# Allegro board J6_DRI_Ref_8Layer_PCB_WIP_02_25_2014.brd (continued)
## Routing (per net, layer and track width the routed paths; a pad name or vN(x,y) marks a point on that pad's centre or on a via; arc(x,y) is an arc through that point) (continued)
VEVM_5V0: length 5.2
  TOP w0.203: U45.A6 v1(128.31,71.88) ; U45.A9 125.98,71.83
  TOP w0.254: v1(124.78,72.22) U45.A10
  TOP w0.381: C99.2 v2(125.55,69.8) 125.55,70.94 125.98,71.38 125.98,71.83
VIO_PMIC: length 2.4
  TOP w0.254: U45.D9 v1(125.58,74.62)
  TOP w0.381: R192.2 v2(123.14,69.8)
  BOTTOM w0.203: v1(125.58,81.82) 125.46,81.7 R533.1
VOUT1_INTB: length 18
  TOP w0.102: 79.2,62.05 77.55,62.05 77.15,61.66 U52.B11
  TOP w0.127: 79.2,62.05 79.32,61.93 82.31,61.93 82.7,62.31 84.37,62.31 85.19,61.48 86.14,61.48 87.28,62.63 93.96,62.63
VPP: length 0.5
  TOP w0.102: U52.K14 v1(71.11,59.65)
VRTC_OUT: length 0.9
  BOTTOM w0.254: v2(126.7,85.8) 126.82,85.68 R514.1
VTT_DDR: length 0.6
  TOP w0.305: C165.1 65.86,30.56
  vias: v2(63.02,17.48) v2(64.8,17.99) v2(65.56,29.03) v2(66.09,18.27) v2(66.95,29.03) v2(106.58,28.53) v2(107.34,29.29)
VUSB_3V3: length 5.9
  TOP w0.127: U52.AA12 U52.Y12
  TOP w0.178: U52.Y12 v1(63.14,61.27)
  TOP w0.203: 125.23,71.77 125.59,72.13 125.59,73.03 U45.B9
  TOP w0.381: 125.23,71.77 124.79,71.33 v1(124.41,71.33) ; v2(124.41,69.8) C433.1
  BOTTOM w0.203: v1(63.14,61.27) 63.8,61.27 C489.1
XTAL1: length 18.9
  TOP w0.127: Y4.3 132.54,64.37 132.54,62.44 132.09,61.99 Y4.1 ; U45.A3 131.06,72.34 131.06,71.99 134.06,68.99 134.06,62.44 133.17,61.55 Y4.1 ; Y4.1 C115.1
XTAL2: length 19
  TOP w0.127: Y4.2 136.29,61.11 135.84,60.66 135.84,58.73 135.46,58.35 ; Y4.2 135.2,61.55 134.32,62.44 134.32,69.12 131.32,72.11 131.32,72.36 U45.A2 ; Y4.2 C116.1
ZQ_DBYTE1: length 4.2
  BOTTOM w0.127: U115.H8 92.99,24.67 89.97,24.67 R694.1
ZQ_DBYTE2: length 4.1
  TOP w0.127: U69.H8 98.58,24.66 99.34,24.66 100.16,25.48 R289.1
ZQ_DBYTE3: length 4.2
  BOTTOM w0.127: R695.1 75.62,24.67 78.64,24.67 U116.H8
ZQ_DBYTE4: length 4.4
  TOP w0.127: R288.1 85.81,25.48 84.99,24.66 84.23,24.66 U68.H8
ZQ_DBYTE4_1: length 1.3
  TOP w0.127: v1(59.05,24.65) U67.H8
  BOTTOM w0.127: R693.1 v1(59.05,24.65)
N35610: length 1.3
  TOP w0.127: U65.L8 v1(35.08,24.89)
  BOTTOM w0.127: R692.1 v1(35.08,24.89)
N35614: length 1.3
  TOP w0.127: U66.L8 v1(47.78,24.89)
  BOTTOM w0.127: R691.1 v1(47.78,24.89)
N17551426: length 0.6
  TOP w0.102: U45.D8 126.78,75.02 v1(126.38,75.42)
N17551447: length 0.6
  TOP w0.254: v1(128.78,77.02) 128.38,77.42 U45.G6
N17551455: length 1.6
  TOP w0.254: U45.C1 132.38,74.22 v1(132.78,73.82)
  BOTTOM w0.305: C403.2 v1(132.78,73.82)
N17551519: length 8.2
  TOP w0.127: U45.A11 124.03,72.27 124.03,71.58 123.52,71.07 123.52,70.31 123.77,70.06 123.77,65.57 R207.2
N17551551: length 0.6
  TOP w0.102: v1(128.78,79.42) 129.18,79.02 U45.J5
N17551822: length 0.6
  TOP w0.102: U45.E6 128.38,75.82 v1(128.78,75.42)
N17551928: length 1.5
  TOP w0.254: v1(127.98,73.82) U45.B7
  BOTTOM w0.305: C100.2 v1(127.98,73.82)
N18507369: length 4.8
  TOP w0.254: v1(127.18,73.82) 127.58,74.22 U45.C7
  TOP w0.381: R193.2 v2(126.7,69.8)
  BOTTOM w0.254: C432.2 127.18,71.17 127.74,71.73 127.74,72.57 127.18,73.12 v1(127.18,73.82)
N19066656: length 8.2
  TOP w0.127: TP42.1 126.11,66.42 126.11,70.23 126.57,70.69 126.57,71.71 126.39,71.88 126.39,73.03 U45.B8
N20019184: length 2.3
  BOTTOM w0.127: C601.1 R685.2 R688.2
N20082076: length 6.2
  TOP w0.127: TP30.1 134.95,83.97 133.43,82.45 133.43,80.86 U45.K1
N20307647: length 0.6
  TOP w0.102: U45.J7 127.58,79.02 v1(127.18,79.42)
N24036072: length 2.3
  BOTTOM w0.127: R687.2 R684.2 C599.1
N27151094: length 0.7
  TOP w0.102: v1(57.61,59.84) U52.AF14
N35662197: length 0.6
  TOP w0.102: v1(123.18,82.62) U45.N12
N42624965: length 0.6
  TOP w0.102: v1(129.59,75.42) U45.E5
N47347830: length 3.2
  TOP w0.102: v1(127.18,78.62) U45.H8
  BOTTOM w0.102: 127.58,79.02 129.15,79.02
  BOTTOM w0.127: v1(127.18,78.62) 127.58,79.02 ; 129.15,79.02 R709.2
N47347885: length 2.7
  TOP w0.102: v1(131.18,81.82) U45.M3
  BOTTOM w0.127: R708.2 132.56,81.85 132.56,81.54 132.38,81.36 131.65,81.36 v1(131.18,81.82)

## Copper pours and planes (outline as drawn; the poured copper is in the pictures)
GND on BOTTOM (solid shape): 33.79,18.48 34.08,18.2 34.48,18.2 34.48,17.95 33.23,17.95 33.23,17.99 33.2,18.07 33.15,18.13 33.03,18.25 32.98,18.29 32.92,18.32 32.89,18.33 32.89,18.42 33.36,18.42 33.68,18.73 33.79,18.73
GND on BOTTOM (solid shape): 40.21,39.69 40.3,39.63 40.28,39.52 38.83,38.06 37.05,38.06 37.05,39.56 37,39.6 36.99,39.66 37.04,39.69
GND on BOTTOM (solid shape): 48.74,48.83 48.8,48.84 48.83,48.79 48.83,48.7 40.35,40.22 34.11,40.22 34.02,40.29 34.04,40.4 34.32,40.68 40.6,40.68
GND on BOTTOM (solid shape): 63.9,46.43 64.01,46.45 64.07,46.36 64.07,46.23 62.74,44.9 61.71,44.9 60.83,44.02 60.78,44 60.74,44.05 60.74,44.16 61.99,45.4 62.87,45.4
GND on BOTTOM (solid shape): 70.4,45.37 70.46,45.46 70.57,45.44 70.6,45.4 72.97,45.4 73.06,45.31 73.07,45.26 73.02,45.23 71.3,45.23 71.05,44.98 70.67,44.98 70.4,45.25
GND on BOTTOM (solid shape): 59.4,19.8 59.47,19.89 59.58,19.86 60.42,19.01 62.68,19.01 62.7,18.95 62.69,18.86 62.61,18.81 60.36,18.81 59.4,19.77
GND on BOTTOM (solid shape): 87.72,34.7 87.78,34.79 87.89,34.77 87.9,34.76 88.56,34.76 88.84,34.48 89.09,34.48 89.09,34 89.17,33.92 89.2,33.81 89.1,33.75 88.66,33.75 88.08,34.33 87.72,34.33
GND on BOTTOM (solid shape): 40.85,25.78 40.97,25.8 41.03,25.7 41.03,25.62 40.76,25.34 39.95,25.34 39.21,24.6 37.36,24.6 37.26,24.67 37.29,24.78 37.8,25.29 39.58,25.29 39.88,25.59 40.67,25.59
GND on BOTTOM (solid shape): 60.86,22.16 60.9,22.13 60.9,22.08 60.87,22.05 60.85,22.01 60.63,21.8 60.62,21.79 60.36,21.63 60.33,21.32 60.34,21.31 60.34,21.25 60.2,21.25 59.37,22.09 59.4,22.16
GND on BOTTOM (solid shape): 43.33,24.83 43.4,24.91 43.51,24.88 43.84,24.55 45.26,24.55 45.52,24.29 45.52,24.26 45.52,24.15 45.56,24.04 45.56,23.94 45.47,23.89 44.25,23.89 43.45,24.69 43.43,24.69 43.35,24.73 43.33,24.82
GND on BOTTOM (solid shape): 62.68,23.51 62.7,23.46 62.72,23.41 62.71,23.31 62.63,23.26 61.57,23.26 61.13,22.82 61.08,22.82 61,22.87 60.98,22.96 60.99,23.04 60.98,23.13 61,23.22 61.08,23.26 61.14,23.26 61.44,23.55 62.68,23.55
GND on BOTTOM (solid shape): 55.38,19.11 55.49,19.13 55.55,19.03 55.55,18.98 55.56,18.92 55.54,18.84 55.46,18.8 51.41,18.8 51.39,18.82 51.38,18.88 51.43,18.91 51.82,18.91 52,19.09 52.25,19.09 52.43,18.91 53,18.91 53.18,19.09 53.43,19.09 53.61,18.91 54.18,18.91 54.36,19.09 54.51,19.09 54.69,18.91 55.17,18.91
GND on BOTTOM (solid shape): 89.11,35.13 89.55,35.13 89.65,35.15 89.74,35.21 89.85,35.33 89.9,35.27 90.02,35.16 89.83,34.96 89.83,34.62 89.85,34.52 89.9,34.43 89.97,34.37 89.93,34.33 89.86,34.29 89.81,34.25 89.62,34.25 89.62,34.73 89.34,35.02 89.06,35.02 88.78,35.3 88.37,35.3 88.27,35.36 88.3,35.47 88.53,35.71
GND on BOTTOM (solid shape): 51.35,25.58 51.37,25.52 51.4,25.47 51.56,25.31 51.64,25.31 51.73,25.27 51.74,25.17 51.7,25 51.74,24.82 51.73,24.72 51.64,24.68 51.08,24.68 50.92,24.53 50.29,24.53 50.14,24.68 50.11,24.68 50.07,24.71 50.08,24.77 50.93,25.62 51.34,25.62
GND on BOTTOM (solid shape): 34.78,19.9 34.83,19.84 34.89,19.79 34.89,19.55 35.2,19.24 37.19,19.24 37.57,19.62 38.2,19.62 38.53,19.29 39.12,19.29 39.4,19.57 39.6,19.57 39.83,19.34 39.85,19.23 39.76,19.17 38.99,19.17 38.63,18.81 37.67,18.81 37.42,19.07 36.5,19.07 36.32,18.89 36.1,18.89 35.92,19.07 34.98,19.07 34.91,19.13 34.91,19.37 34.55,19.73 34.53,19.84 34.62,19.9
GND on BOTTOM (solid shape): 26.31,28.42 26.42,28.44 26.48,28.35 26.48,27.32 26.79,27.01 27.7,27.01 28.51,27.83 28.84,27.83 28.93,27.77 28.91,27.65 28.82,27.57 28.82,26.99 28.59,26.76 26.69,26.76 26.47,26.92 26.2,26.94 26.11,26.96 26.07,27.04 26.07,28.19
GND on BOTTOM (solid shape): 38.8,47.47 38.8,47.3 38.82,47.2 38.88,47.11 39,46.98 39.09,46.92 39.19,46.9 39.4,46.9 39.49,46.92 39.58,46.97 39.59,46.99 39.66,46.99 39.66,46.92 39.68,46.81 39.74,46.73 39.76,46.71 39.77,46.65 39.73,46.62 39,46.62 38.43,47.19 36.76,47.19 36.53,46.95 35.75,46.95 35.75,47.24 35.82,47.31 36.25,47.31 36.51,47.56 38.7,47.56
GND on BOTTOM (solid shape): 46.42,38.58 46.7,38.29 47.26,38.29 47.3,38.2 47.3,38.15 47.26,38.13 46,38.13 45.91,38.03 45.82,38 45.75,38.05 45.36,38.26 44.97,38.03 44.9,37.98 44.81,38.01 44.77,38.05 45.53,38.8 46.42,38.8
GND on BOTTOM (solid shape): 51.44,40.71 51.53,40.74 51.6,40.69 51.65,40.63 51.69,40.57 51.87,40.39 51.98,40.31 52.11,40.24 52.17,40.17 52.14,40.08 51.4,39.34 50.68,39.34 49.94,38.6 48.28,38.6 48.19,38.57 48.12,38.63 48.1,38.65 48.11,38.75 48.19,38.8 48.29,38.8 48.58,39.08 48.58,39.28 50.02,39.28
GND on BOTTOM (solid shape): 30.12,36.7 30.23,36.72 30.29,36.63 30.29,33.75 29.18,33.75 28.81,33.38 28.78,33.34 28.75,33.29 28.7,33.24 28.63,33.23 28.47,33.23 28.33,33.16 28.32,33.15 28.25,33.15 28.02,33.38 27.7,33.4 27.61,33.41 27.57,33.49 27.57,34.16
GND on BOTTOM (solid shape): 22.98,28.89 23.07,28.89 23.12,28.84 23.14,28.77 23.11,28.7 22.54,28.13 22.54,27.4 22.73,27.21 22.75,27.1 22.66,27.04 22.56,27.04 22.45,27.02 22.37,26.96 22.16,26.76 22.16,26.5 22.1,26.4 21.99,26.42 21.85,26.56 21.98,26.69 22.04,26.77 22.06,26.88 22.06,28.87 22.55,28.87 22.78,29.1
GND on BOTTOM (solid shape): 70.12,44.53 70.18,44.62 70.29,44.6 70.44,44.45 71.11,44.45 71.19,44.41 71.21,44.32 71.22,43.93 71.45,43.62 71.45,43.15 71.19,42.71 71.33,42.21 71.34,42.2 71.34,42.13 71.18,42.13 70.12,43.19
GND on BOTTOM (solid shape): 39.98,22.5 39.96,22.48 39.84,22.13 40.03,21.81 40.03,21.53 39.85,21.25 39.91,20.92 39.91,20.82 39.82,20.77 39.47,20.77 39.25,20.99 36.62,20.99 36.55,21.05 36.53,21.16 36.63,21.22 38.51,21.22 39.86,22.57 39.98,22.57
GND on BOTTOM (solid shape): 43.41,20.21 43.5,20.15 43.49,20.05 43.46,20 43.44,19.94 43.38,19.88 43.3,19.88 42.9,19.84 42.79,19.45 42.78,19.36 42.7,19.32 42.31,19.32 41.98,18.99 40.08,18.99 39.99,19.08 39.98,19.13 40.03,19.17 42.01,19.17 43.06,20.21
GND on BOTTOM (solid shape): 34.53,19.21 34.53,18.97 34.6,18.91 34.62,18.8 34.52,18.74 34.49,18.74 34.4,18.78 34.39,18.87 34.26,19.29 33.83,19.27 33.46,19.27 33.14,18.95 32.56,18.95 32.48,19.03 32.47,19.08 32.52,19.12 33.16,19.12 33.45,19.41 33.47,19.41 33.62,19.46 33.73,19.57 34.17,19.57
GND on BOTTOM (solid shape): 33.73,25.91 33.84,25.91 33.92,25.87 33.94,25.78 33.94,25.6 34.03,25.45 34.05,25.37 34.02,25.3 33.95,25.22 33.9,25.13 33.89,25.1 33.73,25.1 33.71,25.13 33.47,25.38 33.12,25.38 33.03,25.39 32.98,25.46 32.7,25.75 32.36,25.75 32.27,25.81 32.29,25.92 32.34,25.97 33.66,25.97
GND on BOTTOM (solid shape): 79.45,21.27 79.53,21.23 79.55,21.14 79.55,20.97 79.64,20.83 79.64,20.65 80.97,19.32 81.64,19.32 81.67,19.27 81.72,19.23 81.75,19.12 81.65,19.05 80.74,19.05 80.66,19.09 80.64,19.18 80.55,19.5 80.24,19.61 80.21,19.6 79.22,20.59 79.22,20.83 79.32,20.97 79.32,21.14 79.33,21.23 79.42,21.27
GND on BOTTOM (solid shape): 93.8,21.27 93.88,21.23 93.9,21.14 93.9,20.97 93.99,20.83 93.99,20.65 95.32,19.32 95.99,19.32 96.03,19.27 96.07,19.23 96.1,19.12 96,19.05 95.09,19.05 95.01,19.09 94.99,19.18 94.9,19.5 94.59,19.61 94.56,19.6 93.57,20.59 93.57,20.83 93.67,20.97 93.67,21.14 93.69,21.23 93.77,21.27
GND on BOTTOM (solid shape): 24.72,22.31 24.79,22.28 25.5,21.58 27.18,21.58 27.26,21.53 27.27,21.44 27.31,21.09 27.63,20.95 27.65,20.96 28.12,20.49 28.85,20.49 29.05,20.28 29.09,20.28 29.11,20.22 28.85,19.95 28.58,19.95 28.41,20.13 27.88,20.13 27.7,19.95 25.79,19.95 25.62,20.13 25.62,20.59 25.32,20.88 24.86,20.88 24.51,21.24 24.51,21.29 24.67,21.45 24.73,21.53 24.75,21.63 24.75,21.8 24.73,21.9 24.67,21.99 24.59,22.07 24.56,22.15 24.59,22.22 24.62,22.25 24.64,22.27
GND on BOTTOM (solid shape): 30.14,32.59 30.38,32.42 30.68,32.43 30.69,32.44 30.75,32.44 30.75,32.32 29.91,31.49 29.83,31.46 29.76,31.5 29.46,31.64 29.18,31.46 29.17,31.44 29.09,31.44 29.04,31.47 29.05,31.52 29.19,31.66 29.22,31.69 29.24,31.72 29.29,31.77 29.36,31.77 29.77,31.9 29.74,32.32 29.74,32.48 29.8,32.53 29.85,32.59
GND on BOTTOM (solid shape): 77.16,35.98 77.19,35.88 77.13,35.81 76.84,35.44 77.03,35.01 77.03,34.78 76.65,34.41 76.06,34.41 76,34.46 75.98,34.57 76.07,34.63 76.47,34.63 76.67,34.83 76.73,34.92 76.75,35.02 76.75,35.19 76.73,35.29 76.67,35.38 76.53,35.51 76.67,35.65 76.73,35.73 76.75,35.83 76.75,36 76.73,36.1 76.67,36.19 76.64,36.21 76.62,36.33 76.72,36.39 76.75,36.39
GND on BOTTOM (solid shape): 53.94,47.51 54.02,47.48 54.04,47.39 54.07,47.17 54.22,47.01 54.22,47 54.38,46.85 54.37,46.82 54.36,46.73 54.36,46.63 54.37,46.61 54.03,46.27 54.01,46.27 53.35,45.91 53.47,45.17 53.52,45.12 53.53,45.07 53.48,45.04 52.66,45.04 52.47,44.85 52.32,44.99 52.34,45.03 52.39,45.48 52.02,45.75 51.93,45.81 51.96,45.92 52.97,46.93 53.17,46.93 53.76,47.51
GND on BOTTOM (solid shape): 82.26,20.92 82.37,20.94 82.44,20.84 82.44,20.67 82.28,20.29 82.59,20.02 82.6,20.02 82.65,19.98 82.58,19.87 82.55,19.87 82.43,19.84 82.33,19.77 82.26,19.74 82.19,19.77 81.9,19.86 81.64,19.7 81.13,19.7 80.76,20.07 80.75,20.13 80.8,20.16 80.85,20.16 81.2,20 81.49,20.25 81.55,20.31 81.62,20.31 81.98,20.4 82.08,20.75 82.1,20.84 82.18,20.88 82.23,20.88
GND on BOTTOM (solid shape): 96.61,20.92 96.72,20.94 96.79,20.84 96.79,20.67 96.63,20.29 96.94,20.02 96.95,20.02 97,19.98 96.93,19.87 96.9,19.87 96.78,19.84 96.68,19.77 96.61,19.74 96.54,19.77 96.25,19.86 95.99,19.7 95.48,19.7 95.11,20.07 95.1,20.13 95.15,20.16 95.2,20.16 95.55,20 95.85,20.25 95.9,20.31 95.98,20.31 96.33,20.4 96.43,20.75 96.45,20.84 96.53,20.88 96.58,20.88
GND on BOTTOM (solid shape): 34.35,42.1 34.63,42.1 34.73,42.12 34.82,42.18 34.95,42.31 35.08,42.18 35.17,42.12 35.27,42.1 35.44,42.1 35.54,42.12 35.63,42.18 35.76,42.31 35.9,42.18 35.98,42.12 36.09,42.1 36.25,42.1 36.36,42.12 36.44,42.18 36.58,42.31 36.71,42.18 36.8,42.12 36.9,42.1 37.07,42.1 37.17,42.12 37.26,42.18 37.39,42.31 37.52,42.18 37.61,42.12 37.71,42.1 37.88,42.1 37.98,42.12 38.07,42.18 38.2,42.31 38.34,42.18 38.42,42.12 38.52,42.1 38.69,42.1 38.79,42.12 38.88,42.18 39.02,42.32 39.16,42.18 39.24,42.12 39.34,42.1 40.07,42.1 40.07,41.75 40.35,41.47 40.39,41.47 40.48,41.4 40.46,41.29 40.38,41.21 34.1,41.21 33.92,41.03 33.81,41.01 33.74,41.1 33.74,42.36 34.1,42.36
GND on BOTTOM (solid shape): 31.69,18.14 31.74,18.06 31.74,17.7 32.02,17.41 32.57,17.41 32.76,17.61 32.88,17.49 32.96,17.43 33.07,17.41 33.43,17.41 33.52,17.36 33.5,17.25 33.72,16.52 34.31,17 34.37,17.1 34.49,17.08 34.51,17.06 35.52,17.06 35.58,17.12 35.62,17.07 35.63,17.06 36.18,16.73 36.51,17.29 36.53,17.37 36.61,17.41 39.19,17.41 39.32,17.54 39.59,17.54 39.72,17.41 42.03,17.41 42.11,17.37 42.13,17.29 42.13,17.06 42.23,16.87 42.25,16.77 42.18,16.7 41.99,16.61 41.84,16.46 41.37,16.46 40.64,16.7 40.2,16.08 40.2,15.83 40.22,15.64 40.3,15.48 40.3,15.37 40.21,15.32 30.12,15.32 30.02,15.38 30.05,15.49 30.19,15.7 30.24,15.95 30.24,16.21 30.18,16.48 30.01,16.7 29.98,16.8 30.04,16.87 30.28,17.1 30.31,17.43 30.32,17.52 30.4,17.57 30.93,17.57 31.51,18.14 31.56,18.15 31.6,18.16
GND on BOTTOM (solid shape): 63.75,45.15 63.86,45.17 63.92,45.08 63.92,39.87 63.88,39.8 63.8,39.77 63.63,39.77 63.47,39.7 63.39,39.68 63.33,39.72 63.1,39.9 62.81,39.97 62.56,39.97 62.27,39.9 62.05,39.72 61.98,39.68 61.91,39.7 61.65,39.78 61.39,39.7 61.28,39.69 61.23,39.78 61.23,40.32 61,40.55 61,42.06 61.04,42.14 61.13,42.16 61.32,42.15 61.5,42.22 61.58,42.24 61.64,42.2 61.7,42.13 61.77,42.07 61.77,41.6 61.54,40.87 62.15,40.43 62.41,40.43 63.02,40.87 62.79,41.6 62.79,42.07 63.02,42.8 62.41,43.25 62.15,43.25 61.87,43.18 61.64,42.99 61.58,42.96 61.5,42.97 61.32,43.05 61.13,43.04 61.04,43.06 61,43.14 61,43.43 61.64,44.07 61.74,44.1 61.81,44.03 62.36,43.7 62.7,44.24 62.72,44.33 62.8,44.36 62.96,44.36
GND on BOTTOM (solid shape): 99.49,31.75 99.58,31.74 99.63,31.66 99.63,29.89 99.59,29.8 99.5,29.79 99.44,29.81 99.38,29.81 99.31,29.83 99.28,29.9 98.76,30.05 98.99,29.56 99.03,29.54 99.04,29.5 99.04,29.44 98.96,29.36 98.94,29.36 98.77,28.85 99.28,29.02 99.28,29.04 99.37,29.12 99.44,29.13 99.5,29.14 99.59,29.13 99.63,29.05 99.63,28.61 99.4,28.39 99.32,28.36 99.24,28.41 98.95,28.56 98.7,28.34 98.62,28.27 98.53,28.3 98.47,28.35 98.46,28.36 98.15,28.56 97.89,28.3 97.85,28.23 97.79,28.21 97.78,28.21 97.71,28.23 97.68,28.3 97.64,28.41 97.56,28.5 97.52,28.57 97.55,28.65 97.63,28.73 97.63,28.89 97.66,28.94 97.67,28.98 97.74,29.05 97.84,29.02 97.9,28.97 97.9,28.96 98.4,28.85 98.29,29.34 98.28,29.34 98.22,29.4 98.19,29.5 98.26,29.57 98.48,29.91 98.16,30.16 98.09,30.19 98.06,30.26 98.09,30.33 98.16,30.36 98.37,30.43 98.48,30.62 98.48,30.64 98.57,30.72 98.63,30.73 98.67,30.71 98.69,30.67 99.14,30.4 99.11,30.93 99.05,31.01 99.08,31.1 99.42,31.43 99.42,31.72
GND on BOTTOM (solid shape): outline of 483 points within 42.72,15.32 63.52,19.5
GND on BOTTOM (solid shape): outline of 1981 points within 82.98,18.37 97.86,36.87
GND on BOTTOM (solid shape): outline of 3469 points within 55.35,15.32 85.24,41
GND on L2-GND1, L7-GND2: 169.24,181.94 169.24,13.46 0.76,13.46 0.76,181.94
VDD_CORE on TOP, BOTTOM: 129.62,89.74 133.81,89.74 134.32,90.25 134.32,95.33 133.93,95.71 129.49,95.71 129.11,95.33 129.11,90.25
VDD_CORE on L4-PWR1: 69.04,61.04 80.34,72.34 99.26,72.34 111.71,84.79 133.81,84.79 134.32,85.3 134.32,95.71 133.81,96.22 129.24,96.22 128.73,95.71 128.73,92.28 107.77,92.28 95.58,80.09 67.64,80.09 60.78,73.23 60.78,64.09 63.7,61.17 63.7,58.24 63.96,57.99 64.34,57.99 64.59,57.74 64.59,55.58 64.85,55.32 65.74,55.32 65.99,55.58 65.99,57.23 66.37,57.61 66.88,57.61 69.04,59.77
VDD_CORE on L5-PWR2: 68.66,60.02 65.61,60.02 65.35,59.77 65.35,58.24 65.99,57.61 65.99,56.09 66.12,55.96 71.32,55.96 71.45,56.09 71.45,57.61 71.58,57.74 72.34,57.74 72.34,60.53 72.09,60.78 71.32,60.78 71.07,60.53 71.07,59.77 70.82,59.51 69.16,59.51
VDD_DDR on TOP: 116.03,79.45 116.03,83.9 115.77,84.15 112.22,84.15 111.71,83.64 111.71,79.83 112.09,79.45
VDD_DDR on BOTTOM: 111.71,79.33 115.65,79.33 115.9,79.58 115.9,83.9 115.77,84.03 111.84,84.03 111.33,83.52 111.33,79.71
VDD_DDR on L4-PWR1: 17.22,26.49 15.57,26.49 14.94,25.86 14.94,23.19 15.44,22.68 17.86,22.68 27.2,13.34 106.1,13.34 110.29,17.53 110.29,29.49 107.57,32.21 100.66,32.21 100.15,32.72 100.15,46.56 101.3,47.7 118.19,47.7 121.49,51.01 121.49,83.77 120.85,84.41 111.96,84.41 107.52,79.96 107.52,79.71 107.77,79.45 117.42,79.45 117.42,69.67 104.98,57.23 93.8,57.23 87.71,51.13 75.39,51.13 72.34,54.18 66.37,54.18 65.48,55.07 64.72,55.07 64.34,55.45 64.34,57.61 64.21,57.74 61.8,57.74 61.54,57.48 61.54,56.21 59.51,56.21 58.88,56.85 48.03,56.85 46.81,55.63 46.81,53.93 43.38,50.5 34.37,50.5 21.79,37.92 21.03,37.92 19,35.89 19,28.27
VDD_DSPEVE_IVA_GPU on TOP: 140.16,74.88 144.09,74.88 144.48,75.26 144.48,83.64 144.22,83.9 140.41,83.9 139.9,83.39 139.9,75.14
VDD_DSPEVE_IVA_GPU on L5-PWR2: 61.8,56.97 58.62,60.15 52.93,60.15 50.27,62.82 50.27,83.42 56.34,89.49 143.33,89.49 144.86,87.96 144.86,75.26 144.48,74.88 139.65,74.88 139.4,75.14 139.4,78.82 139.14,79.07 111.84,79.07 88.72,55.96 73.36,55.96 73.36,57.48 72.97,57.86 72.47,57.86 72.47,60.66 72.21,60.91 71.2,60.91 70.82,60.53 70.82,59.9 70.56,59.64 69.29,59.64 68.78,60.15 65.48,60.15 65.23,59.9 65.23,58.12 65.74,57.61 65.74,56.09 65.61,55.96 64.72,55.96 64.47,56.21 64.47,56.85 64.34,56.97
VDD_MPU on TOP: 116.03,78.95 116.03,69.29 115.77,69.04 111.96,69.04 111.71,69.29 111.71,78.56 112.09,78.95
VDD_MPU on BOTTOM: 116.03,79.2 116.03,69.42 115.52,68.91 112.22,68.91 111.71,69.42 111.71,79.2
VDD_MPU on L4-PWR1: 117.04,79.2 106.63,79.2 99.52,72.09 80.47,72.09 69.29,60.91 69.29,59.51 67.13,57.36 66.37,57.36 66.24,57.23 66.24,54.69 66.5,54.43 72.34,54.43 75.26,51.51 87.33,51.51 93.55,57.74 104.85,57.74 117.04,69.93
VDD_RTC on BOTTOM: 132.66,60.66 135.2,60.66 135.59,61.04 135.59,64.98 134.95,65.61 133.55,65.61 132.66,66.5 132.66,70.06 131.27,71.45 129.74,71.45 129.11,70.82 129.11,62.56 131.65,62.56 131.65,61.67
VDDR_VREFSTL on TOP: 48.56,54.69 48.56,53.42 48.08,53.42 44.02,49.35 34.87,49.35 21.54,36.02 21.54,21.03 27.51,15.06 57.61,15.06 57.86,14.81 57.86,13.79 57.61,13.54 27,13.54 20.02,20.53 20.02,36.15 34.37,50.5 43.38,50.5 47.57,54.69
VDDR_VREFSTL on TOP: 76.23,28.15 77.11,28.15 77.37,27.89 77.37,16.97 77.11,16.72 76.23,16.72 75.97,16.97 75.97,27.89
VDDR_VREFSTL on TOP: 90.58,28.15 91.47,28.15 91.72,27.89 91.72,16.97 91.47,16.72 90.58,16.72 90.32,16.97 90.32,27.89
VDDR_VREFSTL on BOTTOM: 62.31,55.32 62.56,55.58 62.56,56.54 62,57.1 62,57.53 61.8,57.74 54.31,57.74 53.8,57.23 50.11,57.23 49.73,56.85 49.23,56.85 49.1,56.72 49.1,55.83 49.23,55.7 49.86,55.7 50.24,55.32
VDDR_VREFSTL on BOTTOM: 100.1,28.02 100.99,28.02 101.24,27.76 101.24,16.97 100.99,16.72 72.09,16.72 68.91,13.54 21.67,13.54 17.6,17.6 17.6,18.11 18.24,18.75 18.75,18.75 22.43,15.06 68.02,15.06 71.07,18.11 85.24,18.11 85.5,18.37 85.5,27.76 85.75,28.02 86.64,28.02 86.89,27.76 86.89,18.37 87.15,18.11 99.59,18.11 99.85,18.37 99.85,27.76
VDDS_1V8 on TOP: 124.66,97.11 128.22,97.11 128.6,96.73 128.6,90.25 128.09,89.74 124.66,89.74 124.28,90.12 124.28,96.73
VDDS_1V8 on BOTTOM: 124.28,96.73 124.66,97.11 128.22,97.11 128.6,96.73 128.6,90.25 128.09,89.74 124.66,89.74 124.28,90.12
VDDS_1V8 on L4-PWR1: 95.33,80.34 107.77,92.79 127.97,92.79 128.35,93.17 128.35,97.23 127.97,97.61 104.72,97.61 91.9,84.79 59.77,84.79 48.08,73.1 48.08,59.52 48.09,59.52 48.09,57.83 48.82,57.1 59,57.1 59.64,56.47 61.29,56.47 61.29,57.61 61.67,57.99 63.2,57.99 63.45,58.24 63.45,61.04 60.53,63.96 60.53,73.36 67.51,80.34
VDDS_1V8 on L5-PWR2: 58.37,62.82 69.8,62.82 70.05,63.07 70.05,64.21 69.8,64.47 64.72,64.47 63.58,65.61 58.12,65.61 56.59,67.13 53.54,67.13 53.29,66.88 53.29,65.1 53.54,64.85 56.34,64.85
VDDS_1V8 on L5-PWR2: 52.48,59.9 58.5,59.9 61.67,56.72 64.21,56.72 64.34,56.59 64.34,55.96 64.59,55.7 71.45,55.7 71.58,55.83 71.58,57.48 71.7,57.61 72.97,57.61 73.1,57.48 73.1,52.4 72.72,52.02 51.89,52.02 50.75,53.16 50.75,57.33 50.32,57.76 48.49,57.76 48.11,58.14 48.11,60.33 48.51,60.73 51.66,60.73 52.07,60.33 52.07,60.3
(no net) on BOTTOM: 169.24,181.94 169.24,13.46 0.76,13.46 0.76,181.94
Net_296 on BOTTOM: 127.46,74.37 127.84,73.99 129.11,73.99 129.51,73.59 130.23,73.59 130.76,74.12 130.76,74.98 130.48,75.26 128.47,75.26 128.22,75.01 128.22,74.75 127.58,74.75 127.46,74.63
SMPS_7 on TOP: 139.9,74.12 139.9,70.44 140.28,70.06 144.35,70.06 144.6,70.31 144.6,74.25 144.35,74.5 140.28,74.5
SMPS_7 on BOTTOM: 144.35,74.5 140.28,74.5 139.9,74.12 139.9,70.44 140.28,70.06 144.35,70.06 144.6,70.31 144.6,74.25
SMPS_8 on TOP: 123.52,89.87 123.77,90.12 123.77,96.6 123.27,97.11 117.55,97.11 116.66,96.22 116.66,90.25 117.04,89.87
SMPS_8 on BOTTOM: 123.39,89.87 123.77,90.25 123.77,96.6 123.27,97.11 117.55,97.11 116.66,96.22 116.66,90.25 117.04,89.87
SW1 on TOP: 121.49,73.48 122,73.99 122,74.75 122.5,75.26 124.16,75.26 124.54,75.64 124.54,75.9 124.41,76.02 121.36,76.02 119.71,74.37 117.42,74.37 117.04,73.99 117.04,70.18 117.42,69.8 119.71,69.8 121.49,71.58
SW2 on TOP: 124.41,76.41 124.54,76.53 124.54,76.79 124.16,77.17 122.63,77.17 122.38,77.42 122.38,77.68 121.87,78.18 120.98,78.18 120.22,78.95 117.42,78.95 117.04,78.56 117.04,75.26 117.42,74.88 119.71,74.88 121.23,76.41
SW3 on TOP: 122.25,78.82 124.41,78.82 124.54,78.95 124.54,79.71 124.28,79.96 122.89,79.96 122,80.85 122,83.01 120.73,84.28 117.42,84.28 117.04,83.9 117.04,79.83 117.42,79.45 120.22,79.45 121.11,78.56 122,78.56
SW4 on TOP: 132.54,76.91 130.89,76.91 130.63,77.17 130.63,77.55 130.76,77.68 134.19,77.68 134.82,78.31 135.71,78.31 136.35,78.95 138.51,78.95 138.89,78.56 138.89,75.26 138.51,74.88 134.57,74.88
SW5 on TOP: 130.76,78.06 130.63,78.18 130.63,78.31 131.14,78.82 132.79,78.82 133.17,79.2 133.17,80.09 133.81,80.72 133.81,81.99 136.47,84.66 138.51,84.66 138.89,84.28 138.89,79.83 138.51,79.45 136.22,79.45 135.59,78.82 134.7,78.82 133.93,78.06
SW6 on TOP: 128.98,81.23 129.74,81.23 130,81.49 130,82.76 130.25,83.01 132.66,83.01 134.32,84.66 134.32,88.34 133.93,88.72 129.49,88.72 129.11,88.34 129.11,86.82 129.24,86.69 129.24,84.91 128.85,84.53 128.85,81.36
SW7 on TOP: 130.63,75.14 130.63,74.63 130.89,74.37 132.79,74.37 133.17,73.99 133.17,71.58 134.44,70.31 138.25,70.31 138.89,70.94 138.89,73.99 138.51,74.37 134.44,74.37 133.68,75.14
SW8 on TOP: 125.3,81.23 125.04,81.23 124.79,81.49 124.79,81.61 124.28,82.12 124.28,82.88 124.03,83.14 122.63,83.14 120.98,84.79 119.46,84.79 119.08,85.17 119.08,87.45 120.35,88.72 123.65,88.72 124.03,88.34 124.03,85.42 125.55,83.9 125.55,81.49
SW9 on TOP: 128.47,81.99 127.71,81.23 127.46,81.23 126.82,81.87 126.82,82.76 126.57,83.01 126.19,83.01 125.93,83.26 125.93,84.15 124.54,85.55 124.54,88.34 124.92,88.72 128.22,88.72 128.6,88.34 128.6,86.69 128.73,86.57 128.73,85.04 128.47,84.79
VEVM_3V3 on L4-PWR1: 122,70.56 122,83.77 122.63,84.41 134.06,84.41 134.82,85.17 134.82,96.09 134.06,96.85 132.41,96.85 132.28,96.73 131.01,96.73 130,97.74 130,103.33 132.03,105.36 147.14,105.36 148.29,104.22 148.29,70.44 147.4,69.55 123.01,69.55
VIO_PMIC on BOTTOM: 121.62,68.79 121.74,68.66 124.54,68.66 124.66,68.79 124.66,69.42 124.16,69.93 124.16,71.45 124.54,71.83 124.54,72.39 124.38,72.54 124.38,73.61 124.64,73.87 124.66,73.87 125.04,74.25 125.55,74.25 125.81,74.5 125.81,74.96 125.55,74.96 125.25,75.26 125.25,75.69 125.04,75.9 123.65,75.9 122.76,75.01 122.76,74.37 121.62,73.23
VTT_DDR on TOP: 64.72,28.27 64.72,18.87 64.47,18.62 63.32,18.62 62.69,17.99 62.69,17.35 62.94,17.1 66.62,17.1 67.64,18.11 67.64,29.54 65.99,31.19 64.72,31.19 64.47,30.94 64.47,28.53
VTT_DDR on TOP: 106.07,28.15 106.07,18.87 105.82,18.62 104.6,18.62 103.96,17.99 103.96,17.35 104.22,17.1 107.9,17.1 108.92,18.11 108.92,28.91 107.26,30.56 106.07,30.56 105.82,30.3 105.82,28.4
VTT_DDR on BOTTOM: 106.07,28.53 106.07,18.87 105.82,18.62 104.72,18.62 103.96,17.86 103.96,17.35 104.22,17.1 107.9,17.1 108.92,18.11 108.92,28.91 108.15,29.67 107.21,29.67
VTT_DDR on BOTTOM: 65.61,29.67 64.85,28.91 64.59,28.91 64.47,28.78 64.47,18.62 63.45,18.62 62.69,17.86 62.69,17.35 62.94,17.1 66.57,17.1 67.64,18.11 67.64,29.29 67.26,29.67

Small or netless copper shapes (teardrops, artwork), in the pictures only: 53 on BOTTOM

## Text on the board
BOTTOM: LOGIC 516582 REV D | PWB 516581 REV C | LAYER 16 | SOLDER
Ref Des/Assembly Bottom: 1
Board Geometry/Soldermask Bottom: SMS
Ref Des/Silkscreen Bottom: GND | 39 | 1 | 2 | 120 | 119 | 40 | EXPANSION | LCD | INTERFACE | MICRO-SD | BSLK
User.Comments: AUSTIN,TEXAS 78756 | 4410 SHOALWOOD | (512)260-5778 | TURNING CONCEPT | INTO REALITY | PWB 516581 REV C
Board Geometry/Outline: 5-3-13 | BREAK OFF TAB
TOP: COMPONENT | LAYER 1
Ref Des/Assembly Top: CONN.CABLE
Board Geometry/Soldermask Top: SMC
Ref Des/Silkscreen Top: 1 | GND | USB-ID | CAN1 | 12V-FAN | A1 | DCAN1 | LEOPARD IMAGING | PB/WAKE | USB1 | AH1 | AH28 | ETHERNET 0 | A28 | ETHERNET 1 | 2 | 19 | LCD CONNECTOR | DCAN2 | LEDS | USER | B1 | HDMI | DAUGHTER CARD | CONN1 | DAUGHTER | CARD | CONN3 | PWR-RESET | 20 | MIC IN | CPU-RESET | LINE IN | LINE OUT | PMIC | 12V | 5 | HEADPHONE | PWR-INA | OUT | PCIe CONNECTOR | USB2 | MIPI-60 | DC | POWER | AUDIO | AREA | SATA | ETHERNET | FPD-LINK | TERMINAL | USERCONFIG | COM MODULE | MLB/MLBP | ASSY 516580 REV | VAYU EVM | XC5777X CPU BOARD | S/N | SYSBOOT | [0-15] | TSLK
L2-GND1: LAYER 2 | GROUND
L3-SIGNAL: LAYER 3 | SIGNAL
L4-PWR1: LAYER 4 | GROUND
L5-PWR2: LAYER 5 | SIGNAL
L6-SIGNAL: LAYER 6 | GROUND
L7-GND2: LAYER 7 | SIGNAL
DIMENSION: 2 PLCS
USER_PART_NUM_BOTTOM: BSLKC
USER_PART_NUM_TOP: TSLKC
DISPLAY_BOTTOM: SPS
DISPLAY_TOP: conn.mtg holes | 39 | 40 | SPC
User.8: CHECK PLOT ONLY
User.12: R282 | R343 | R69 | R527 | R248 | C198 | R250 | C193 | R472 | C226 | C308 | C330 | C197 | C406 | C224 | C298 | C352 | C466 | R227 | R459 | C219 | R526 | R451 | C313 | C285 | R76 | R284 | L25 | L26 | C274 | C213 | R279 | U69 | C156 | R408 | U88 | 39 | C442 | 1 | C164 | C165 | C233 | U70 | J13 | J15 | R615 | C157 | C163 | R517 | 2 | C465 | R554 | C209 | R287 | R524 | C221 | U86 | C218 | C440 | C454 | C453 | R519 | R520 | 40 | C391 | C392 | C393 | R312 | R419 | C382 | R333 | R335 | R480 | E7 | C207 | R275 | R283 | R285 | R286 | R291 | R311 | R310 | R309 | R321 | R320 | C316 | C68 | R457 | R532 | R528 | R556 | R32 | R458 | R373 | RN32 | U89 | R491 | R498 | U77 | U74 | RT1 | R562 | R619 | R331 | C331 | R465 | C351 | C356 | R477 | C498 | C497 | R307 | R433 | R436 | R443 | C504 | R448 | C225 | C258 | C506 | C460 | C133 | R622 | U78 | R396 | R296 | C236 | U66 | C280 | C261 | C505 | C273 | C293 | R567 | R319 | C254 | C489 | R314 | C494 | C260 | U76 | C459 | RN22 | R607 | C300 | C357 | R225 | R421 | R422 | R426 | R428 | R442 | R449 | R453 | R456 | R461 | R464 | R467 | R470 | R476 | C304 | C311 | R623 | J12 | C458 | R389 | R376 | R386 | U91 | R485 | R608 | R487 | R230 | R439 | R446 | C332 | R261 | R455 | R460 | R463 | R466 | R475 | R479 | R388 | R387 | U68 | C158 | R431 | R223 | R281 | C216 | R438 | R445 | R577 | C286 | R424 | R427 | C305 | R441 | R224 | R447 | R462 | R468 | R474 | R478 | R482 | R484 | R486 | R488 | R490 | R420 | C435 | U65 | C238 | R260 | U94 | C517 | R99 | 120 | 119 | J14 | R83 | R278 | C252 | R553 | U75 | C493 | C244 | E4 | C275 | C418 | C403 | C411 | U83 | R552 | R322 | R277 | R356 | R359 | U93 | R259 | R366 | R371 | R378 | R393 | R400 | R243 | E5 | C181 | R252 | C204 | C188 | R545 | C277 | C456 | R543 | C195 | R399 | R344 | R342 | R299 | C167 | C276 | R406 | R410 | R414 | C203 | R301 | R329 | R293 | R298 | R341 | R489 | R493 | R500 | R501 | U79 | R454 | R437 | R469 | R595 | R375 | U84 | R251 | C513 | C187 | C230 | C245 | C501 | C223 | C337 | R518 | C363 | C377 | J17 | R521 | C231 | R89 | R601 | R413 | U67 | C217 | C263 | C343 | R440 | R412 | R542 | R544 | R546 | R269 | R274 | C317 | R345 | C214 | R346 | R348 | R349 | R509 | R508 | R599 | C166 | C192 | J16 | C242 | C259 | R495 | R423 | R411 | R160 | C490 | R253 | C410 | C417 | R305 | R246 | R473 | C194 | R304 | C416 | R513 | R303 | C232 | R471 | C212 | C271 | R512 | R523 | R578 | R300 | R511 | U90 | R579 | C237 | C270 | C412 | C211 | R280 | C514 | R418 | R272 | R425 | R510 | R80 | C210 | C269 | R294 | R537 | C227 | C201 | U64 | R78 | R536 | C262 | R573 | R74 | R551 | R266 | R535 | R572 | C191 | C415 | R534 | R571 | C408 | C297 | R271 | C162 | R533 | C414 | R570 | R429 | R525 | C206 | C220 | C407 | C413 | R42 | C229 | C161 | C155 | R43 | C205 | C200 | C228 | R614 | C199 | R222 | C202 | C436 | C457 | TP54 | C390 | C463 | R318 | R616 | R483 | R416 | R380 | C462 | R379 | C64 | R317 | RN34 | RN33 | R384 | RN31 | C355 | R315 | R383 | RN27 | C389 | C428 | R316 | R382 | R334 | C402 | RN28 | C461 | R432 | R270 | RN26 | C483 | R306 | R330 | RN29 | R288 | RN30 | C507 | R332 | C400 | C310 | R308 | C338 | C409 | R297 | C290 | C404 | R397 | C376 | C179 | R313 | C268 | C375 | C267 | C178 | R336 | C495 | C496 | C485 | C481 | C257 | C384 | R481 | E3 | C256 | C467 | C255 | R606 | C396 | C484 | C395 | E2 | C333 | C486 | C478 | R402 | C253 | C488 | C472 | R263 | R207 | C340 | C383 | C471 | E1 | R352 | R262 | C482 | C476 | R100 | C464 | C379 | R108 | R609 | C282 | R367 | R231 | R220 | R381 | C479 | R101 | C284 | R377 | C474 | C283 | R110 | C289 | R226 | R109 | C368 | R126 | C487 | R385 | RN25 | R228 | C208 | R276 | C159 | R574 | C405 | C424 | C160 | R273 | R531 | R268 | R549 | R515 | R522 | R292 | C251 | C430 | C250 | C241 | C249 | C248 | R496 | R265 | C512 | C185 | R505 | C184 | R499 | C243 | R350 | R450 | R233 | C247 | R354 | C240 | R229 | C169 | R353 | C174 | C183 | R530 | R328 | R492 | R232 | C173 | C182 | R238 | C180 | C235 | R327 | R290 | C176 | R326 | R289 | C172 | R325 | R529 | C508 | R324 | R323 | C171 | R258 | C190 | C234 | C189 | R374 | E6 | R370 | R504 | C239 | R503 | C246 | C398 | C399 | R365 | R502 | R507 | R364 | C397 | R363 | R362 | R361 | R257 | C215 | R360 | C170 | C186 | R576 | C175 | C196 | R575 | C222 | U85 | R240 | C500 | R357 | R256 | R255 | R369 | R347 | R404 | R444 | R239 | R254 | R452 | R245 | R244 | C168 | C177 | R600 | +
User.14: 2 | 1
User.18: AUSTIN,TEXAS 78756 | 4410 SHOALWOOD | (512)260-5778 | TURNING CONCEPT | INTO REALITY | DATE | DESIGN ENGR | PROJECT ENGR | ENGR MGR | NEXT ASSEMBLY | APPROVED | CHECKED | DRAFTING | ENGR | NONE | 1 OF 1 | VIEW | SCALE: NONE | XC5777X CPU BOARD | LAYER 7 | LAYER 8 | LAYER 9 | LAYER 10 | LAYER 11 | LAYER 12 | LAYER 13 | LAYER 14 | LAYER 15 | LAYER 16 | LAYER 1 | LAYER 2 | 100 OHM DIFFERENTIAL +/-10%: 3.5 MIL TRACE BY 7.0 MIL SPACE EXTERNAL. | 100 OHM DIFFERENTIAL +/-10%: 3.0 MIL TRACE BY 6.0 MIL SPACE INTERNAL. | 10.  IMPEDENCE CONTROL: | 1.  TOTAL BOARD THICKNESS SHALL BE .080 +/- 10% INCHES. | 4.  SOLDERMASK ON BOTH SIDES OF THE BOARD SHALL BE S.M.O.B.C., LPI, COLOR GREEN. | 2.  COPPER WEIGHT OF OUTER LAYERS AFTER PLATING SHALL BE THE EQUIVALENT | 3.  MINIMUM CLEARANCE ON THE BOARD SHALL BE 3.0 MILS. | 5.  PLATED THRU HOLE SIZE TOLERANCES SHALL BE +/- .003 INCH. | 6.  DRC'S MUST BE RUN ON THE GERBERS BEFORE BUILDING BOARDS UNLESS PRIOR | 7.  FINISHED BOARD SHALL BE FREE OF BURRS ON EDGES. | 8.  SURFACE FINISH SHALL BE IMMERSION GOLD. | 9.  ALL SIGNAL EXTERNAL 5 MIL TRACES TO BE CONTROLLED IMPEDANCE, 50 OHMS SINGLE ENDED. | 90 OHM DIFFERENTIAL +/-10%: 4.5 MIL TRACE BY 5.5 MIL SPACE EXTERNAL. | 90 OHM DIFFERENTIAL +/-10%: 5.0 MIL TRACE BY 7 MIL SPACE INTERNAL. | ALL MATERIAL SHALL BE NEMA GRADE FR-4 OR EQUIVALENT. (Tg>=170 DEG. C) | OF 0.5OZ. COPPER. INTERNAL LAYERS 2 AND 15 SHALL BE 2.0OZ. COPPER. REMAINING | INTERNAL LAYERS SHALL BE 0.5OZ. COPPER. AVERAGE COPPER ON THE WALL OF THE | UNPLATED THRU HOLE SIZE TOLERANCES SHALL BE +/- .002 INCH. | PLATED HOLE SHALL BE PER IPC CLASS 2. | MINIMUM TRACE WIDTH ON THE BOARD SHALL BE 3.0 MILS. | LAYER 3,14  4.5  MIL TRACES TO BE CONTROLLED IMPEDANCE, 50 OHMS SINGLE ENDED. | LAYER 5,12  4    MIL TRACES TO BE CONTROLLED IMPEDANCE, 50 OHMS SINGLE ENDED. | LAYER 7,10  3.3  MIL TRACES TO BE CONTROLLED IMPEDANCE, 50 OHMS SINGLE ENDED. | LAYER 3     3.01 MIL TRACES TO BE CONTROLLED IMPEDANCE, 60 OHMS SINGLE ENDED. | APPROVAL IS GIVEN IN WRITING. | ALL SIGNAL EXTERNAL 3.51 MIL TRACES TO BE CONTROLLED IMPEDANCE, 60 OHMS SINGLE ENDED. | NOTES: UNLESS OTHERWISE SPECIFIED | A | A-A
User.19: C100 | R534 | R533 | R535 | R483 | C352 | C347 | C541 | C528 | C484 | C502 | C517 | C504 | C509 | C516 | C477 | C507 | C490 | C491 | C497 | C469 | C508 | C518 | C467 | C498 | C486 | C403 | C343 | R709 | C407 | R513 | R537 | R514 | R516 | C462 | C520 | C458 | C457 | C519 | C471 | C388 | C489 | C512 | C386 | C481 | C495 | C468 | C485 | C475 | C480 | R271 | R273 | C186 | R272 | R274 | C187 | TP64 | R292 | TP61 | TP45 | TP39 | TP52 | R67 | C84 | R736 | R735 | C136 | C96 | C137 | C385 | TP8 | R261 | TP7 | TP10 | TP50 | R256 | C692 | R245 | TP11 | TP51 | TP53 | R658 | TP58 | R237 | R243 | TP14 | TP56 | R231 | U120 | R259 | R263 | TP60 | TP21 | TP26 | R258 | TP19 | TP34 | TP42 | TP43 | C142 | R215 | R553 | C380 | C375 | C353 | C339 | C338 | C432 | C346 | C354 | C341 | R639 | R648 | R655 | R662 | C342 | R395 | R398 | R661 | R666 | C691 | R663 | R640 | R649 | R656 | R542 | R545 | R550 | R556 | R563 | R571 | R582 | R602 | R609 | R613 | R543 | R546 | R551 | R586 | R595 | R598 | R611 | R614 | R572 | R557 | R564 | C649 | R544 | R547 | R552 | R370 | R375 | R377 | R381 | C104 | C412 | C418 | C425 | R632 | C460 | C548 | R376 | C384 | C413 | C419 | C426 | C436 | C368 | C465 | C556 | C367 | C365 | C650 | C483 | C473 | R386 | C265 | C414 | C420 | C427 | C549 | C396 | C400 | C557 | C255 | C369 | C366 | C474 | C466 | C94 | C253 | C91 | R382 | C370 | C260 | C118 | C119 | C392 | R618 | R624 | C92 | C391 | C526 | C482 | C542 | C437 | C444 | C506 | C361 | C501 | C249 | C248 | C245 | C246 | C242 | C478 | R538 | C492 | C439 | C505 | C463 | C127 | C510 | C422 | C429 | C110 | R587 | C479 | C448 | C201 | R214 | TP63 | TP48 | R714 | TP27 | C126 | TP55 | R738 | R740 | R742 | R744 | R746 | R748 | R737 | R739 | R741 | R743 | R745 | R747 | C32 | C171 | R288 | C178 | C185 | R731 | R131 | TP54 | TP59 | R730 | R732 | R110 | R111 | TP9 | R112 | R113 | R114 | R115 | R269 | C159 | R116 | C163 | R289 | TP29 | R120 | R121 | R122 | R123 | R124 | R125 | R191 | R209 | R210 | R211 | C433 | C99 | R193 | C431 | C134 | C101 | C141 | C102 | C103 | R201 | R518 | R708 | C680 | C376 | C379 | R622 | R18 | R16 | R15 | R700 | C642 | C628 | C636 | C664 | C651 | C666 | C667 | C668 | C669 | C562 | C644 | C595 | C630 | R694 | C615 | C652 | C629 | C637 | C401 | R629 | C674 | R625 | C675 | R378 | C523 | C399 | C676 | C677 | C247 | C355 | R399 | C364 | C395 | C500 | C356 | C438 | C496 | C493 | C494 | C537 | C390 | C359 | C363 | C372 | C393 | C445 | C360 | C394 | C398 | C524 | C442 | C90 | C487 | C443 | C397 | C456 | C529 | C89 | C373 | C449 | C530 | C602 | C362 | C589 | C374 | C461 | C371 | C470 | C464 | C402 | 1 | U17 | R291 | J16 | R244 | J2 | TP46 | TP49 | GND | U56 | 2 | USB-ID | U11 | SW1 | C149 | CAN1 | U16 | U12 | C155 | R129 | R133 | R136 | R137 | R139 | 12V-FAN | TP4 | R104 | J7 | R277 | C179 | R98 | R99 | R293 | R178 | U74 | U35 | U54 | C39 | R75 | U41 | J9 | J10 | J12 | TP5 | U48 | C36 | C31 | A1 | U46 | TP65 | TP6 | R200 | R196 | L4 | DCAN1 | JP1 | U36 | U43 | U1 | U9 | C68 | C70 | LEOPARD IMAGING | R27 | R185 | R7 | R1 | T1 | C210 | C73 | C75 | R6 | TP2 | PB/WAKE | Y5 | RU24 | U65 | C203 | C262 | R154 | C80 | Y3 | L8 | C87 | R179 | C682 | C211 | A9 | T9 | USB1 | E1 | C64 | C65 | C106 | E2 | RU31 | C681 | C212 | C113 | R722 | RU40 | E3 | U66 | E9 | C204 | Y6 | U26 | R30 | R33 | R39 | R41 | R47 | R52 | R190 | C213 | R195 | C143 | U15 | R66 | R68 | C107 | C148 | C83 | C59 | U10 | C194 | R96 | C43 | C214 | R61 | C37 | AH1 | AH28 | C40 | R97 | R31 | R34 | R40 | R42 | R48 | R53 | C34 | BGA WITHOUT SKT OUTLINE | U67 | C205 | R183 | U27 | RN2 | C55 | RN6 | RN4 | ETHERNET 0 | C175 | C180 | C165 | RN1 | C147 | U7 | R727 | R728 | R465 | C169 | R729 | R444 | C177 | C184 | R725 | TP12 | R28 | C293 | R468 | C199 | C25 | C26 | A28 | C44 | U68 | C21 | R726 | U18 | R72 | R73 | C41 | C195 | Y1 | E4 | C85 | R132 | R43 | R49 | R54 | ETHERNET 1 | E5 | C24 | R718 | SW2 | R128 | R242 | R56 | TP25 | R44 | R50 | R55 | C67 | R37 | R130 | C30 | E6 | R224 | TP16 | TP20 | TP13 | TP15 | R221 | U69 | R156 | C18 | R38 | RU19 | C196 | C146 | R188 | R189 | R197 | R198 | R202 | R212 | R217 | R235 | R248 | U62 | TP17 | DCAN2 | R199 | R203 | R213 | R218 | R220 | R225 | R232 | RU21 | R717 | JP3 | U61 | C98 | C122 | R2 | U6 | U25 | C135 | R5 | C4 | R286 | R270 | C14 | C176 | U38 | C12 | R3 | R229 | R233 | R268 | R240 | C15 | RU49 | C23 | C69 | C82 | R247 | L1 | JTAG | U2 | R754 | C16 | C2 | R181 | TP62 | R46 | C35 | U39 | R4 | C29 | U118 | U57 | 19 | U14 | R22 | DS1 | DS2 | DS3 | L13 | L3 | U3 | U58 | TP24 | R149 | TP32 | RU5 | E7 | DS4 | LCD CONNECTOR | C60 | L6 | C7 | L9 | R11 | J4 | E8 | C74 | R126 | USER | LEDS | R257 | R260 | R262 | R266 | R144 | R143 | L10 | TP31 | C131 | R472 | C76 | L11 | L19 | C47 | TP30 | U59 | R151 | Y4 | Q1 | Q3 | U37 | F1 | Q4 | R145 | C78 | U51 | Q2 | R147 | R281 | R146 | R234 | R239 | C133 | R287 | U8 | C97 | U55 | C153 | L21 | R440 | R449 | R127 | U47 | TP3 | C51 | C684 | C72 | C77 | C61 | L7 | R619 | R569 | R579 | R585 | R594 | R599 | R601 | R604 | R610 | R612 | R710 | R461 | C304 | C536 | R450 | R701 | C299 | C377 | C349 | U105 | C513 | C329 | C316 | R456 | C63 | C435 | C301 | C306 | R463 | C330 | R580 | R702 | C62 | R453 | C305 | C309 | R697 | C647 | R654 | R659 | R664 | R668 | U90 | R475 | R672 | Q5 | C302 | C326 | R451 | R671 | R464 | C307 | C327 | C215 | C568 | R675 | C575 | C558 | R660 | U91 | R673 | R422 | R423 | R426 | R638 | R647 | R665 | R414 | C328 | R428 | R749 | R674 | R676 | R677 | R682 | R383 | R384 | C236 | R750 | C216 | U106 | R567 | R35 | R751 | C488 | C459 | R332 | C318 | C235 | C333 | C378 | C410 | R474 | C350 | RU82 | U22 | R391 | R596 | C251 | R623 | U107 | R364 | R458 | C241 | U98 | R401 | U102 | U119 | U92 | R392 | U97 | U77 | RU88 | C476 | R407 | C274 | C280 | R427 | R433 | R17 | R343 | C383 | U78 | RU93 | C321 | C308 | C334 | RU103 | RU108 | C601 | C626 | C634 | R685 | R688 | U79 | R345 | R466 | R340 | R14 | C310 | R641 | R626 | C298 | R459 | R719 | R467 | 40 | R652 | C573 | U83 | C665 | 119 | EXP_P3 | R657 | 120 | R653 | R296 | R540 | U115 | R294 | U80 | C294 | R755 | R634 | R635 | R627 | R651 | C670 | 39 | R650 | R354 | R358 | R360 | R366 | R371 | C105 | R394 | R396 | R397 | R400 | R720 | R297 | R379 | R385 | R388 | R390 | R633 | R314 | RU94 | C453 | C673 | R380 | C95 | C322 | C226 | C108 | R350 | R355 | R359 | R361 | R367 | R372 | C93 | R330 | R328 | U116 | C678 | R298 | R436 | R295 | C616 | C631 | U28 | C643 | C627 | C635 | C599 | R299 | RN11 | C311 | C284 | R684 | R320 | R687 | R689 | C323 | R469 | U84 | C227 | C640 | RN17 | RN13 | R441 | R329 | R331 | C578 | C590 | R470 | C312 | R307 | C283 | C632 | U72 | C454 | R693 | R721 | C263 | C282 | C270 | R541 | C217 | C267 | R347 | C625 | C633 | C641 | C514 | RU96 | C324 | Y7 | C521 | R352 | C563 | C451 | C258 | C580 | C250 | R362 | R368 | R373 | C597 | C610 | C623 | C522 | R691 | C511 | C452 | C559 | C440 | C348 | C612 | U70 | C117 | R216 | R480 | C336 | R363 | R369 | R374 | C600 | C313 | R204 | C618 | R439 | R471 | C416 | C423 | R530 | R620 | C358 | EXP_P1 | R529 | C611 | R531 | R605 | C417 | C424 | R692 | R300 | RN9 | U73 | R415 | C613 | C624 | R308 | C256 | C266 | C264 | R321 | C261 | R448 | C583 | R630 | R322 | RN10 | R71 | L23 | RU89 | R353 | C619 | R532 | C638 | C605 | C268 | R301 | R481 | R305 | R421 | C254 | R581 | R669 | R584 | C1 | C525 | R645 | R600 | C257 | R713 | R593 | C446 | R603 | C230 | R615 | C547 | C331 | U112 | R528 | R517 | R597 | R515 | R539 | C275 | U110 | C279 | C288 | C604 | C345 | R568 | C335 | C411 | C405 | C332 | C292 | R325 | U114 | R323 | U104 | C658 | C579 | R460 | C351 | R617 | R324 | C607 | C515 | R326 | C272 | C532 | AUSTIN,TEXAS 78756 | 4410 SHOALWOOD | (512)260-5778 | C188 | C192 | C202 | L20 | R255 | R21 | R275 | R219 | R227 | C130 | C152 | C646 | R478 | R339 | R536 | R548 | C572 | TP22 | TP44 | R76 | 100 | RU13 | U64 | U63 | R241 | R290 | JP2 | U75 | 99 | FL5 | TP47 | R106 | R715 | C150 | R278 | R282 | TP23 | R148 | R279 | R283 | R222 | FL6 | R280 | R284 | R276 | C157 | R285 | Y2 | FL7 | U50 | B1 | FL8 | R157 | C3 | C42 | HDMI | C123 | C66 | SW7 | R29 | C79 | C259 | C120 | C86 | R58 | R59 | R62 | C125 | R63 | L12 | FL1 | R64 | R65 | R79 | C124 | C128 | FL2 | DAUGHTER CARD | C193 | TP57 | C182 | R60 | CONN1 | R78 | U44 | R77 | FL3 | R223 | RU42 | R267 | C183 | FL4 | R177 | C53 | R182 | R74 | R184 | R36 | C27 | R100 | R107 | C48 | RU32 | TP37 | R101 | R108 | TP1 | R158 | C206 | R102 | C164 | R103 | R160 | C58 | TP38 | C207 | R161 | R163 | R164 | R165 | C56 | R109 | R166 | TP40 | R105 | R167 | C545 | C197 | C57 | R168 | C450 | R733 | RU33 | R169 | C17 | R170 | C160 | R442 | C20 | C28 | C54 | R171 | C46 | R443 | R26 | R172 | U109 | R173 | R69 | R174 | C22 | C111 | C138 | R175 | C389 | C109 | U117 | C158 | R32 | R176 | C112 | C387 | C139 | R80 | C162 | C189 | C33 | C38 | R81 | R82 | C140 | R236 | C170 | C198 | R24 | TP28 | R83 | C161 | TP18 | TP33 | R84 | R85 | TP35 | C19 | C200 | RU4 | R86 | C145 | DAUGHTER | CARD | U60 | RU29 | CONN3 | U20 | C190 | R87 | R117 | TP36 | C172 | R88 | R118 | R119 | C208 | RN3 | RN5 | RN7 | RU30 | U121 | C166 | C181 | C209 | C129 | C167 | C9 | R246 | R264 | R180 | R265 | C88 | R230 | SW3 | PWR-RESET | CPU-RESET | C10 | R89 | C11 | R90 | R716 | R91 | R92 | 20 | L2 | C685 | R93 | L15 | L17 | C690 | R8 | R94 | R205 | C5 | U53 | R95 | MIC IN | R206 | C6 | R207 | R208 | C689 | C683 | C71 | TP41 | C121 | R194 | R192 | P10 | R134 | C8 | LINE IN | C52 | C13 | R20 | R10 | R9 | C115 | R140 | P11 | C173 | R153 | R13 | C45 | R12 | L18 | LINE OUT | C49 | C116 | R152 | C151 | C50 | C81 | C168 | C114 | L14 | L16 | R138 | P12 | L22 | SW8 | U34 | R155 | R135 | C132 | R249 | PMIC | R250 | R251 | R252 | 5 | R253 | R254 | HEADPHONE | P13 | PWR-INA | R696 | R573 | R574 | R575 | R576 | R577 | R578 | C303 | C295 | R642 | C409 | C314 | R683 | R643 | C565 | R454 | R678 | R455 | C566 | R644 | R142 | C300 | R680 | C567 | R679 | U101 | R457 | R141 | R681 | R549 | C408 | C430 | R476 | C381 | R338 | C317 | R588 | C231 | R589 | C232 | R590 | C234 | R333 | R565 | C434 | R591 | C543 | R566 | R592 | C228 | R570 | R404 | R405 | C252 | C229 | C320 | C273 | R406 | C269 | R753 | R429 | R417 | C441 | C499 | C544 | R327 | R473 | C233 | C319 | R304 | R703 | R554 | C290 | R410 | C297 | R19 | R704 | R555 | RU99 | C421 | R341 | R583 | R616 | R342 | R698 | C428 | R686 | R705 | R752 | R706 | R699 | R344 | R707 | C653 | C660 | RU111 | RU113 | C661 | TP66 | RN12 | RN14 | RN16 | R724 | C550 | C592 | C551 | C552 | R670 | C581 | C224 | C315 | R667 | R310 | R621 | R309 | R311 | C553 | R402 | R312 | C554 | R313 | C218 | C555 | R403 | R346 | C219 | C585 | C239 | C671 | C220 | C238 | C672 | C593 | R349 | U85 | R484 | R408 | C582 | R485 | R486 | R186 | R409 | R487 | C271 | R488 | C281 | R357 | R489 | C225 | R490 | C455 | R435 | C586 | R491 | R446 | R315 | RU95 | R492 | C679 | R447 | C596 | R695 | C645 | R493 | C561 | R316 | R437 | C221 | R494 | R317 | R438 | C655 | R495 | R318 | C222 | C289 | R496 | C656 | R319 | R497 | C657 | C223 | R498 | C654 | R499 | R500 | C662 | C285 | R501 | C584 | R303 | R502 | C663 | RN15 | R306 | R503 | C576 | R432 | R348 | R504 | C564 | R302 | C237 | R505 | C614 | R723 | C577 | R506 | C571 | C240 | R507 | C608 | R508 | C574 | R387 | R509 | C609 | R510 | C591 | R511 | C243 | C603 | R512 | C617 | C406 | R525 | C570 | C621 | R526 | C382 | C357 | R527 | C337 | C415 | C538 | R365 | C539 | C587 | C606 | C639 | U71 | RN8 | C533 | C622 | R356 | C598 | C534 | C535 | C296 | C594 | R636 | R631 | R637 | R416 | C588 | R70 | C340 | C325 | R712 | R519 | R711 | R690 | R628 | C344 | C404 | C447 | R646 | C540 | R479 | R559 | C527 | R560 | R561 | C531 | R562 | R420 | R520 | R521 | R413 | R434 | R522 | C659 | R523 | C472 | R524 | C291 | R462 | C503 | C278 | U100 | R558 | C546 | C174 | C156 | C191 | C154 | R238 | R150 | R226 | R228 | R187 | C144 | C620 | R606 | R607 | R608 | R482 | R477 | C648 | C569 | C560 | TURNING CONCEPT | INTO REALITY | OUT | P8 | P4 | J11 | P7 | PCIe CONNECTOR | P2 | J5 | USB2 | ETHERNET | AREA | U52 | P5 | P6 | J14 | J13 | DC | POWER | AUDIO | J3 | U23 | INTERFACE | J15 | LCD | DATE | DESIGN ENGR | PROJECT ENGR | ENGR MGR | NEXT ASSEMBLY | APPROVED | CHECKED | DRAFTING | ENGR | EXP_P2 | EXPANSION | 1 OF 1 | P9 | SATA | P3 | J1 | TERMINAL | P1 | SW4 | SW6 | FPD-LINK | U45 | J8 | SW5 | USERCONFIG | MICRO-SD | P14 | COM MODULE | MLB/MLBP | ASSY 516580 REV | VAYU EVM | XC5777X CPU BOARD | S/N | SYSBOOT | [0-15] | + | ASSEMBLY SOLDER SIDE
User.20: AUSTIN,TEXAS 78756 | 4410 SHOALWOOD | (512)260-5778 | TURNING CONCEPT | INTO REALITY | NONE
User.21: AUSTIN,TEXAS 78756 | 4410 SHOALWOOD | (512)260-5778 | TURNING CONCEPT | INTO REALITY
User.22: 1 | J18 | 2 | J19 | 41 | 42 | J17 | 79 | 80 | 119 | 120
User.23: 1. All board outlines shall be .020 in width. | 2. All other lines shall be .012 in width. | 3. Note and misc. text shall be text block 10. | 4. View and description text shall be text block 16. | 5. Make sure that there is not any double dimensioning, | 6. Check all notes to make sure that they apply and are correct. | 7. Make sure that layer stack-up is correct. | label (REF) dim when needed.
User.25: FIGURE | SIZE | 8.0 | 10.0 | 40.0 | 41.0 | 61.0 | 63.0 | DRILL CHART: TOP to BOTTOM | ALL UNITS ARE IN MILS | PLATED | NON-PLATED | QTY | 135 | 1539 | 2
